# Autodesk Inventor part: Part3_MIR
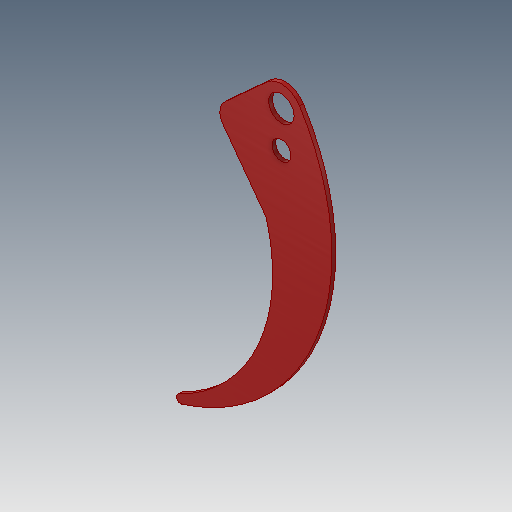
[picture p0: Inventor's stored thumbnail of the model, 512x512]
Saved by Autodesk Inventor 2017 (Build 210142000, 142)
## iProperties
Created: 2016-09
Part Number: Part3_MIR
Material: Generic
Document SubType Name: Modeling
Designer: thh71104
Density: 1 g/cm^3
Appearance: Default
Author: thh71104
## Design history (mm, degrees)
derived "Part3.ipt"
  sketch "Sketch1"
    geometry: L1 (88.821, -35.221)-(22.551, 24.87) reference; L2 (24.034, -159.9)-(92.05, -67.197) reference; L3 (-233.842, 33.572)-(-239.842, 33.572) reference; L4 (-239.842, 33.572)-(-239.842, -481.085) reference; L5 (-233.842, -481.085)-(-233.842, 33.572) reference; C1 r 20 at (0, 0) reference; C2 r 15 at (0, -57) reference; A1 r 336 centre (256.7, -159.9) between (-28.495, 17.75) and (157.133, -480.809) reference; A2 r 33.572 centre (0, 0) between (22.551, 24.87) and (-28.495, 17.75) reference; A3 r 24 centre (72.7, -53) between (92.05, -67.197) and (88.821, -35.221) reference; A4 r 263 centre (276.7, -232.9) between (24.034, -159.9) and (161.648, -469.399) reference; A5 r 6.153 centre (158.956, -474.932) between (157.133, -480.809) and (161.648, -469.399) reference; 1 further point
feature "Solid1::Part3.ipt" dims "d0" = 10
tag "TaggingFeature1"
body "Solid1"
